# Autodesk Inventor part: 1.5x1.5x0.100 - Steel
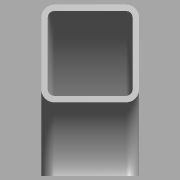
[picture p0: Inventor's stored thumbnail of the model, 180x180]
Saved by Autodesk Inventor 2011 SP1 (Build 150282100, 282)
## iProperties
Created: 2011-03
Part Number: 1.5x1.5x0.100 - Steel
Material: Default
Document SubType Name: Modeling
Designer: bamfomg
Density: 1 g/cm^3
Author: bamfomg
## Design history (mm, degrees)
derived "Square Tube Corners.ipt" dims "d2" = 19.05, "d3" = 19.05, "d6" = 2.54, "d7" = 2.54, "d8" = 2.54, "d12" = 90 deg, "d16" = 1.5875, "d18" = 30 deg, "ID_Rad" = 2.54, "OD_Rad" = 5.08, "Side_One" = 38.1, "Side_Two" = 38.1, "Thickness" = 2.54, "Bend_IDRad" = 28.575, "Bevel_Angl" = 30 deg, "Bevel_Dist" = 1.5875
body "Solid1"
feature "Solid1::Square Tube Corners.ipt" dims "d2" = 19.05, "d3" = 19.05, "d6" = 2.54, "d7" = 2.54, "d8" = 2.54, "d12" = 90 deg, "d16" = 1.5875, "d18" = 30 deg, "ID_Rad" = 2.54, "OD_Rad" = 5.08, "Side_One" = 38.1, "Side_Two" = 38.1, "Thickness" = 2.54, "Bend_IDRad" = 28.575, "Bevel_Angl" = 30 deg, "Bevel_Dist" = 1.5875, "ScaleForDerivedMember" = 10
tag "TaggingFeature1"
